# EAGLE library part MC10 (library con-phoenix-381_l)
Mini-Combicon 3.81mm horizontal 10-polig (ohne Gegenstecker)
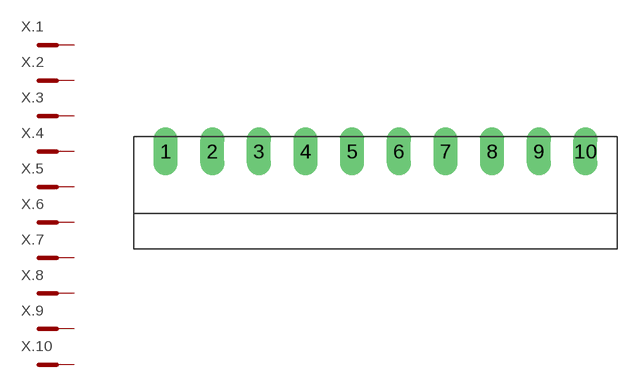
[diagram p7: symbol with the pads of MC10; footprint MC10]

Designator prefix X; gates .1=MCST .2=MCST .3=MCST .4=MCST .5=MCST .6=MCST .7=MCST .8=MCST .9=MCST .10=MCST

## MC10  [MC10]
1  .1:SK  pas
2  .2:SK  pas
3  .3:SK  pas
4  .4:SK  pas
5  .5:SK  pas
6  .6:SK  pas
7  .7:SK  pas
8  .8:SK  pas
9  .9:SK  pas
10  .10:SK  pas

## Footprint MC10 (pad centres in mm)
Mini-Combicon 3.81mm horizontal 10-polig (ohne Gegenstecker)
drill 1.3 long: 1 -17.145,0; 2 -13.335,0; 3 -9.525,0; 4 -5.715,0; 5 -1.905,0; 6 1.905,0; 7 5.715,0; 8 9.525,0; 9 13.335,0; 10 17.145,0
